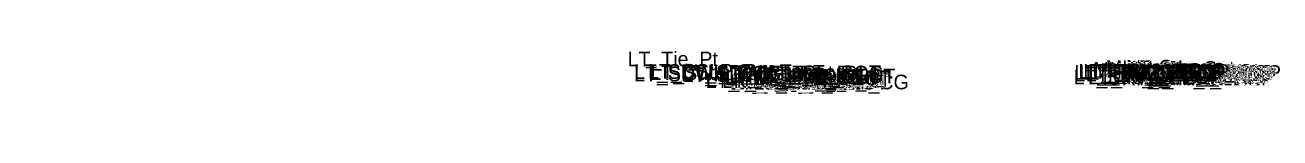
# Model space of a CAD drawing. Extents: x -26 to 4229, y -10 to 9523.
# Drawn here: x 3000 to 3171.5, y 4000 to 4008.4 of the extents above; entities that cross this region are included whole.
import ezdxf

# ---------------------------------------------------------------- set-up
doc = ezdxf.new("R2010")
doc.units = 0
doc.layers.add('Default', color=7, linetype='Continuous')

msp = doc.modelspace()

# ---------------------------------------------------------------- texts
at = {"layer": 'Default'}
for s, height, p in [('LT_Tie_Pt', 2, (3082.37, 4006.27)), ('LT_SDWK_Out_Top', 2, (3083.24, 4004.55)), ('LT_SDWK_Out_Bot', 2, (3083.27, 4004.22)), ('LT_CSLP_Pnt', 2, (3085.17, 4004.58)), ('LT_Sub_Trench_Out_DLT', 2, (3085.49, 4004.38)), ('LT_SDWK_In_Top', 2, (3089.86, 4004.45)), ('LT_SDWK_In_Bot', 2, (3089.89, 4004.12)), ('LT_CG_Top_Face', 2, (3094.76, 4004.34)), ('LT_CG_Top_BOC', 2, (3095.28, 4004.34)), ('LT_CG_Top_Gut', 2, (3095.74, 4003.84)), ('LT_PV2_OEOT', 2, (3099.67, 4003.71)), ('LT_PV1_OEOT', 2, (3100.24, 4003.96)), ('LT_Sub_OEEOP', 2, (3143.35, 4003.81)), ('LT_PV2_OEEOP', 2, (3143.44, 4004.44)), ('LT_PV3_OEEOP', 2, (3143.44, 4004.19)), ('LT_PV1_OEEOP', 2, (3144.01, 4004.56)), ('LT_PV2_IEEOP', 2, (3144.09, 4004.44)), ('LT_PV1_IEEOP', 2, (3144.66, 4004.56)), ('LT_PV2_PGL1', 2, (3145.02, 4004.44)), ('LT_PV3_PGL1', 2, (3145.02, 4004.19)), ('LT_PV2_PGL', 2, (3145.35, 4004.44)), ('LT_PV4_PGL', 2, (3145.35, 4003.81)), ('LT_PV1_PGL', 2, (3145.92, 4004.69)), ('MI_Face In', 2, (3146.04, 4004.85)), ('MI_Bot In', 2, (3147.02, 4004.69)), ('MI_Top In', 2, (3147.75, 4005.1)), ('RT_Sub_OEEOP', 2, (3149.92, 4003.68)), ('RT_PV2_OEEOP', 2, (3150.01, 4004.3)), ('RT_PV3_OEEOP', 2, (3150.01, 4004.05)), ('MI_Crown', 2, (3150.51, 4005.15)), ('RT_PV1_OEEOP', 2, (3150.58, 4004.43)), ('RT_PV2_IEEOP', 2, (3150.66, 4004.3)), ('MI_Face Out', 2, (3151.01, 4004.72)), ('MI_Top Out', 2, (3151.22, 4004.97)), ('RT_PV1_IEEOP', 2, (3151.22, 4004.43)), ('RT_PV2_PGL1', 2, (3151.58, 4004.3)), ('RT_PV3_PGL1', 2, (3151.58, 4004.05)), ('RT_PV2_PGL', 2, (3151.92, 4004.3)), ('RT_PV4_PGL', 2, (3151.92, 4003.68)), ('MI_Bot Out', 2, (3152.01, 4004.55)), ('RT_PV1_PGL', 2, (3152.48, 4004.55)), ('LT_CG1_Shelf_Out', 2, (3093.05, 4003.31)), ('LT_CG_Bot_BOC', 2, (3095.31, 4003.32)), ('LT_Sub_OEOP', 2, (3096.36, 4003.06)), ('LT_Sub_OEOT_CG', 2, (3096.87, 4003.12)), ('LT_CG_Bot_IE', 2, (3099.41, 4003.37)), ('LT_Sub_OEOT', 2, (3099.58, 4003.08)), ('LT_PV3_OEOT', 2, (3099.67, 4003.46)), ('-', 0.0001, (3000, 4000)), ('-', 0.0001, (3000, 4000)), ('-', 0.0001, (3000, 4000)), ('-', 0.0001, (3000, 4000)), ('-', 0.0001, (3000, 4000)), ('-', 0.0001, (3000, 4000)), ('-', 0.0001, (3000, 4000))]:
    msp.add_text(s, height=height, dxfattribs=at).set_placement(p)

doc.saveas('drawing.dxf')
